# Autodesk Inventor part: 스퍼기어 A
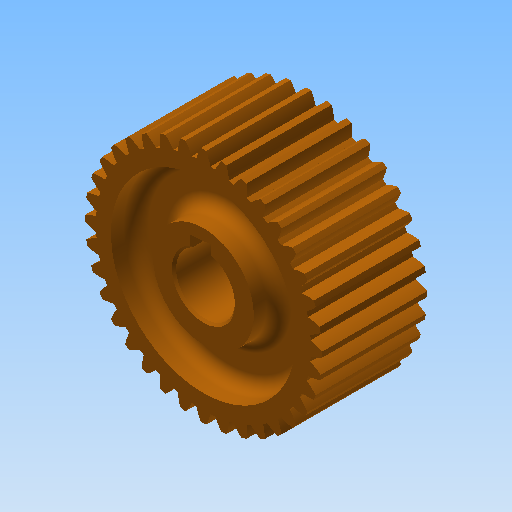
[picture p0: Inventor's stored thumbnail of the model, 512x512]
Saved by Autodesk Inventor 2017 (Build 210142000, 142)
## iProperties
Created: 2020-04
Part Number: 스퍼기어 A
Material: 강철, 연강
Document SubType Name: Modeling
Designer: mduedu
Categories: <?xml version="1.0" encoding="UTF-16"?> <MemberInstance><Categories><FamilyTemplate><FamilyTemplateParameter ValueType="xs:double" Id="1" ObjectReferenceKey="da
Density: 7.86 g/cm^3
Mass: 321.469 g
Surface Area: 147.737 cm^2
Volume: 40.8993 cm^3
Appearance: 주황색
Author: mduedu
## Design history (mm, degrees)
sketch "Sketch1"
  geometry: C1 r 28.2 at (0, 0)
  constraints: 1 centre point
  dimensions: "d0" = 56.4 diameter of C1 (= da_da)
extrude "Extrusion1" new body sketch "Sketch1" distance "d1" = 25 (= da_b); taper "d2" = 0 deg
workplane "Work Plane2"
sketch "Sketch2"
  geometry: C1 r 28.2 at (0, 0) reference; C2 r 27 at (0, 0)
  constraints: 1 centre point, 1 coincident
  dimensions: "d3" = 54 diameter of C2 (= da_dw)
feature "피치 지름" sketch "Sketch2" dims "d4" = 10, "d5" = 0
workplane "Work Plane8"
workplane "Work Plane9"
feature "스퍼 기어" dims "da_b" = 25, "da_d" = 54, "da_aw" = 45, "da_da" = 56.4, "da_df" = 51.129, "da_dw" = 54, angle "da_beta" = 0 deg, "da_lefttooth" = 0, "da_righttooth" = 0
node "작업 평면11"
sketch "스케치3"
  geometry: C1 r 12 at (0, 0); C2 r 22 at (0, 0); 1 further point
  constraints: 2 centre point, 2 coincident
  dimensions: "d49" = 24 diameter of C1; "d50" = 44 diameter of C2
extrude "돌출2" cut sketch "스케치3" distance "d51" = 6; taper "d52" = 0 deg
fillet "모깎기1" dims "d53" = 3
sketch "스케치4" dims "d17" = 0
  geometry: L1 (-3.06, 6.296)-(1.921, 6.731); L2 (1.921, 6.731)-(1.68, 9.483); L3 (1.68, 9.483)-(-3.301, 9.047); L4 (-3.301, 9.047)-(-3.06, 6.296); L5 (-3.728, 42.608)-(3.728, -42.608) reference; A1 r 7 centre (0, 0) between (-3.06, 6.296) and (1.921, 6.731); 1 further point
  constraints: 8 end point, 4 perpendicular, 2 point on circle, 1 centre point, 1 coincident
  dimensions: "d54" = 14 diameter of A1; "d63" = 16.3 dimension on A1 L3; "d64" = 5 distance of L2.end L3.end
extrude "돌출3" cut sketch "스케치4" stored distance "d58" = 6; taper "d59" = 0 deg
chamfer "모따기1" distance "d60" = 0.5; stored, may be unused: second distance "d61" = 2, angle "d62" = 45 deg
body "Solid1"
mirror "대칭1"
body "Srf1"
other parameters: "d16" = 45 (= da_aw), "d34" = 5 deg (computed from da_z), "d39" = 0, "d41" = 0, "d43" = 45 (= da_aw), "d46" = 45 (= da_aw), "d47" = 0, "d48" = 0
